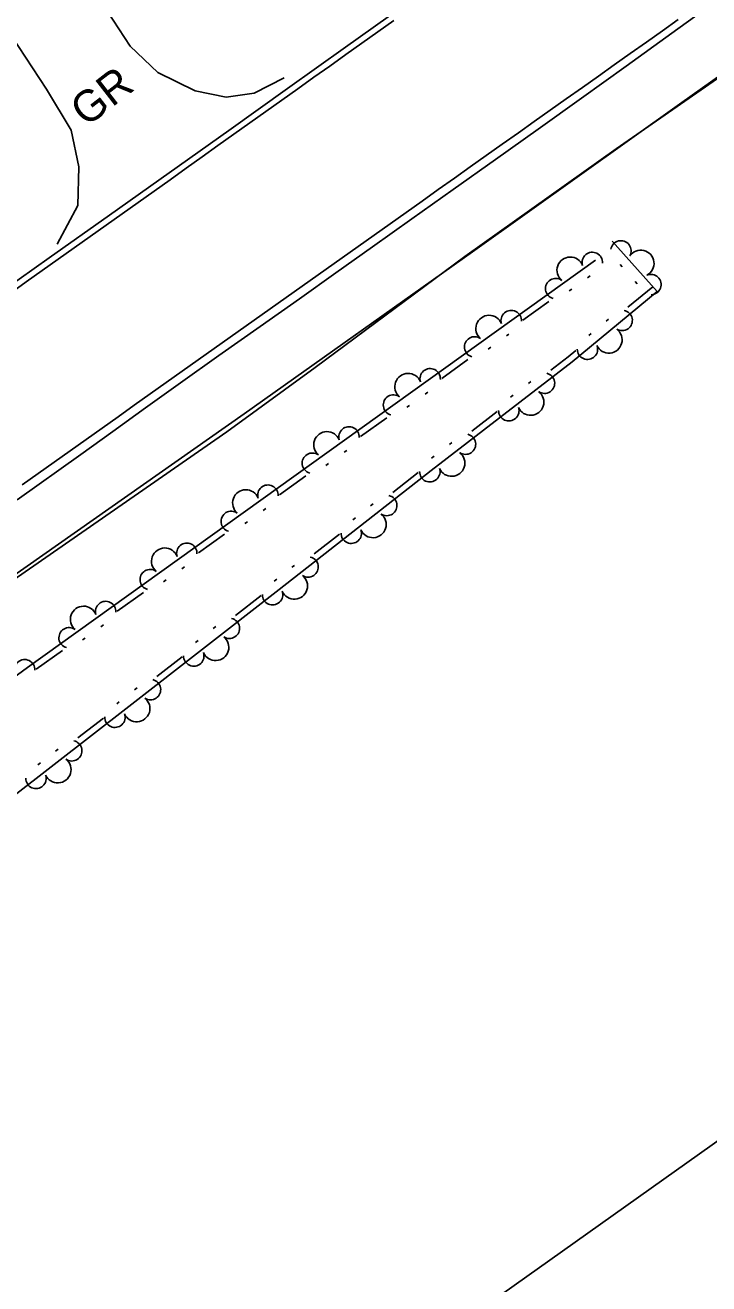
# Model space of a CAD drawing. Extents: x 1577032 to 1581865, y 611492 to 615011.
# Drawn here: x 1580081.3 to 1580168.3, y 613426.5 to 613586.8 of the extents above; entities that cross this region are included whole.
import ezdxf

# ---------------------------------------------------------------- set-up
doc = ezdxf.new("R2010")
doc.units = 0
for name, color, linetype in [('Exist Guardrail', 7, 'Continuous'), ('Exist Right of Way Line', 7, 'Continuous'), ('Exist Roads EOP', 7, 'Continuous'), ('Exist Roads EOT', 7, 'Continuous'), ('Old_Level_11', 7, 'Continuous'), ('Old_Level_7', 7, 'Continuous'), ('Scratch_Level_4', 7, 'Continuous')]:
    doc.layers.add(name, color=color, linetype=linetype)

msp = doc.modelspace()

# ---------------------------------------------------------------- linework, layer by layer
at = {"layer": 'Exist Guardrail'}
msp.add_lwpolyline([(1580204.94, 613604.14), (1580176.13, 613584.66), (1580156.54, 613571.08), (1580137.28, 613557.36), (1580118.21, 613543.22), (1580106.98, 613535), (1580070.56, 613509.77), (1580039.34, 613487.9), (1579996.35, 613458.56), (1579960.14, 613434.1), (1579928.53, 613412.65), (1579891.13, 613387.42), (1579884.09, 613382.52), (1579876.58, 613377.52), (1579866.53, 613371.18), (1579856.35, 613364.93), (1579850.36, 613361.17), (1579845.45, 613357.94), (1579839.56, 613353.95), (1579830.4, 613347.61), (1579818.74, 613338.59)], dxfattribs=at)
at = {"layer": 'Exist Right of Way Line'}
msp.add_line((1578304.92, 612120.6), (1580458.22, 613649.74), dxfattribs=at)
at = {"layer": 'Exist Roads EOP'}
for points in [[(1580129.41, 613589.25), (1580122.09, 613584.03), (1580114.69, 613578.76), (1580107.21, 613573.42), (1580099.64, 613568.03), (1580092.03, 613562.62), (1580084.36, 613557.19), (1580076.66, 613551.75)], [(1580080.28, 613526.36), (1580088.37, 613532.14), (1580092.45, 613535.08), (1580096.62, 613538.08), (1580101.06, 613541.25), (1580105.96, 613544.73), (1580111.21, 613548.44), (1580116.21, 613551.97), (1580120.86, 613555.28), (1580125.51, 613558.58), (1580130.51, 613562.14), (1580135.81, 613565.91), (1580141.19, 613569.73), (1580146.6, 613573.58), (1580152.12, 613577.52), (1580157.81, 613581.61), (1580163.65, 613585.82), (1580169.43, 613589.97)]]:
    msp.add_lwpolyline(points, dxfattribs=at)
at = {"layer": 'Exist Roads EOT'}
for points in [[(1580128.24, 613587.42), (1580126.21, 613585.97), (1580124.17, 613584.52), (1580122.13, 613583.07), (1580120.1, 613581.62), (1580118.06, 613580.18), (1580116.02, 613578.73), (1580113.99, 613577.28), (1580111.95, 613575.83), (1580109.91, 613574.38), (1580107.88, 613572.93), (1580105.84, 613571.49), (1580103.81, 613570.04), (1580101.77, 613568.59), (1580099.73, 613567.14), (1580097.7, 613565.69), (1580095.66, 613564.24), (1580093.62, 613562.8), (1580091.59, 613561.35), (1580089.55, 613559.9), (1580087.51, 613558.45), (1580085.48, 613557), (1580083.44, 613555.55), (1580081.4, 613554.11), (1580079.37, 613552.66)], [(1580080.91, 613528.27), (1580082.95, 613529.72), (1580084.99, 613531.17), (1580087.02, 613532.61), (1580089.06, 613534.06), (1580091.1, 613535.5), (1580093.14, 613536.95), (1580095.18, 613538.4), (1580097.21, 613539.84), (1580099.25, 613541.29), (1580101.29, 613542.73), (1580103.33, 613544.18), (1580105.37, 613545.63), (1580107.4, 613547.07), (1580109.44, 613548.52), (1580111.48, 613549.96), (1580113.52, 613551.41), (1580115.56, 613552.86), (1580117.59, 613554.3), (1580119.63, 613555.75), (1580121.67, 613557.19), (1580123.71, 613558.64), (1580125.75, 613560.09), (1580127.78, 613561.53), (1580129.82, 613562.98), (1580131.86, 613564.42), (1580133.9, 613565.87), (1580135.94, 613567.32), (1580137.97, 613568.76), (1580140.01, 613570.21), (1580142.05, 613571.65), (1580144.09, 613573.1), (1580146.12, 613574.54), (1580148.16, 613575.99), (1580150.2, 613577.44), (1580152.24, 613578.88), (1580154.28, 613580.33), (1580156.31, 613581.77), (1580158.35, 613583.22), (1580160.39, 613584.66), (1580162.43, 613586.11), (1580164.46, 613587.56)]]:
    msp.add_lwpolyline(points, dxfattribs=at)
at = {"layer": 'Old_Level_11'}
for points in [[(1580156.06, 613559.3), (1580161.76, 613552.9), (1580150.95, 613543.94), (1580133.01, 613530.08), (1580113.63, 613514.92), (1580094.48, 613500.02), (1580075.04, 613484.95), (1580051.08, 613466.93), (1580027.89, 613449.31), (1580002.55, 613429.96), (1579984.13, 613415.59), (1579962.72, 613399.84), (1579922.89, 613372.21), (1579876.06, 613342.54), (1579870.92, 613340.95), (1579866.8, 613349.13), (1579884.06, 613361.44), (1579915.37, 613383.81), (1579973.43, 613425.83), (1580032.77, 613469.22), (1580081.59, 613504.98), (1580153.92, 613556.9)], [(1580157.05, 613556.33), (1580157.33, 613556.03)], [(1580152.9, 613554.65), (1580153.23, 613554.89)], [(1580158.96, 613554.19), (1580159.23, 613553.89)], [(1580150.57, 613552.97), (1580150.9, 613553.21)], [(1580161.2, 613553.5), (1580158.05, 613550.88)], [(1580144.66, 613549.24), (1580147.99, 613551.63)], [(1580155.57, 613549.37), (1580155.26, 613549.11)], [(1580142.57, 613547.24), (1580142.9, 613547.47)], [(1580153.36, 613547.54), (1580153.05, 613547.28)], [(1580140.24, 613545.56), (1580140.57, 613545.8)], [(1580134.33, 613541.83), (1580137.67, 613544.22)], [(1580151.41, 613545.39), (1580150.44, 613544.58), (1580148.22, 613542.86)], [(1580145.69, 613541.43), (1580145.37, 613541.18)], [(1580132.24, 613539.82), (1580132.58, 613540.06)], [(1580143.43, 613539.68), (1580143.1, 613539.43)], [(1580129.91, 613538.15), (1580130.24, 613538.39)], [(1580124.01, 613534.42), (1580127.34, 613536.81)], [(1580141.4, 613537.6), (1580138.16, 613535.09)], [(1580135.64, 613533.66), (1580135.31, 613533.41)], [(1580121.91, 613532.41), (1580122.24, 613532.65)], [(1580133.37, 613531.91), (1580133.04, 613531.65)], [(1580119.58, 613530.74), (1580119.91, 613530.98)], [(1580131.35, 613529.82), (1580128.12, 613527.29)], [(1580113.68, 613527), (1580117.01, 613529.4)], [(1580111.58, 613525), (1580111.92, 613525.24)], [(1580125.6, 613525.84), (1580125.28, 613525.59)], [(1580109.25, 613523.32), (1580109.58, 613523.56)], [(1580123.34, 613524.08), (1580123.02, 613523.82)], [(1580103.35, 613519.59), (1580106.68, 613521.98)], [(1580121.33, 613521.98), (1580118.1, 613519.46)], [(1580101.25, 613517.58), (1580101.59, 613517.82)], [(1580115.59, 613518.01), (1580115.26, 613517.76)], [(1580098.92, 613515.91), (1580099.26, 613516.15)], [(1580113.33, 613516.24), (1580113, 613515.99)], [(1580093.02, 613512.18), (1580096.35, 613514.57)], [(1580111.32, 613514.16), (1580108.08, 613511.64)], [(1580090.93, 613510.17), (1580091.26, 613510.41)], [(1580105.56, 613510.2), (1580105.24, 613509.95)], [(1580088.59, 613508.5), (1580088.93, 613508.74)], [(1580103.3, 613508.44), (1580102.97, 613508.19)], [(1580082.69, 613504.77), (1580086.02, 613507.16)], [(1580101.28, 613506.35), (1580098.04, 613503.83)], [(1580095.53, 613502.39), (1580095.2, 613502.14)], [(1580093.26, 613500.63), (1580092.94, 613500.38)], [(1580091.24, 613498.55), (1580088, 613496.04)], [(1580085.48, 613494.6), (1580085.16, 613494.35)], [(1580083.22, 613492.84), (1580082.89, 613492.59)]]:
    msp.add_lwpolyline(points, dxfattribs=at)
for centre, radius, start, end in [((1580157.15, 613558.07), 1.3, 330.1359, 170.9325), ((1580150.7, 613555.6), 1.69, 21.63, 229.7025), ((1580153.51, 613556.6), 1.3, 356.4348, 197.2313), ((1580159.68, 613556.47), 1.69, 297.6647, 145.7372), ((1580148.85, 613553.26), 1.3, 54.1012, 254.8978), ((1580160.97, 613553.78), 1.3, 272.4694, 113.266), ((1580143.18, 613549.19), 1.3, 356.4348, 197.2313), ((1580157.31, 613549.21), 1.3, 238.0866, 78.8832), ((1580140.37, 613548.18), 1.69, 21.63, 229.7025), ((1580155.62, 613546.74), 1.69, 205.6154, 53.6879), ((1580138.52, 613545.84), 1.3, 54.1012, 254.8978), ((1580152.89, 613545.54), 1.3, 180.4202, 21.2167), ((1580130.05, 613540.77), 1.69, 21.63, 229.7025), ((1580132.86, 613541.78), 1.3, 356.4348, 197.2313), ((1580147.42, 613541.21), 1.3, 236.1294, 76.926), ((1580128.19, 613538.43), 1.3, 54.1012, 254.8978), ((1580145.65, 613538.81), 1.69, 203.6582, 51.7307), ((1580142.88, 613537.7), 1.3, 178.4629, 19.2595), ((1580119.72, 613533.36), 1.69, 21.63, 229.7025), ((1580122.53, 613534.37), 1.3, 356.4348, 197.2313), ((1580137.36, 613533.44), 1.3, 236.1294, 76.926), ((1580117.86, 613531.02), 1.3, 54.1012, 254.8978), ((1580135.59, 613531.04), 1.69, 203.6582, 51.7307), ((1580132.82, 613529.93), 1.3, 178.7998, 19.5963), ((1580112.2, 613526.95), 1.3, 356.4348, 197.2313), ((1580109.39, 613525.95), 1.69, 21.63, 229.7025), ((1580127.33, 613525.63), 1.3, 236.4662, 77.2628), ((1580107.53, 613523.61), 1.3, 54.1012, 254.8978), ((1580125.57, 613523.22), 1.69, 203.995, 52.0675), ((1580122.81, 613522.1), 1.3, 178.7998, 19.5963), ((1580099.06, 613518.53), 1.69, 21.63, 229.7025), ((1580101.87, 613519.54), 1.3, 356.4348, 197.2313), ((1580117.31, 613517.8), 1.3, 236.4662, 77.2628), ((1580097.21, 613516.19), 1.3, 54.1012, 254.8978), ((1580115.56, 613515.39), 1.69, 203.995, 52.0675), ((1580112.79, 613514.26), 1.3, 178.6464, 19.4429), ((1580088.73, 613511.12), 1.69, 21.63, 229.7025), ((1580091.54, 613512.13), 1.3, 356.4348, 197.2313), ((1580107.29, 613509.98), 1.3, 236.3128, 77.1094), ((1580086.88, 613508.78), 1.3, 54.1012, 254.8978), ((1580105.53, 613507.57), 1.69, 203.8416, 51.9141), ((1580081.22, 613504.71), 1.3, 356.9968, 197.7934), ((1580102.76, 613506.46), 1.3, 178.6464, 19.4429), ((1580097.25, 613502.18), 1.3, 236.3128, 77.1094), ((1580095.49, 613499.77), 1.69, 203.8416, 51.9141), ((1580092.72, 613498.66), 1.3, 178.5661, 19.3626), ((1580087.21, 613494.38), 1.3, 236.2325, 77.0291), ((1580085.44, 613491.98), 1.69, 203.7613, 51.8338), ((1580082.67, 613490.86), 1.3, 178.5661, 19.3626)]:
    msp.add_arc(centre, radius, start, end, dxfattribs=at)
at = {"layer": 'Old_Level_7'}
msp.add_lwpolyline([(1580204.41, 613605.7), (1580184.66, 613591.04), (1580164.93, 613576.99), (1580138.26, 613557.96), (1580109.19, 613537.33), (1580079.14, 613516.2), (1580044.46, 613491.82), (1580020.63, 613475.12), (1579980.8, 613448.19), (1579942.82, 613422.24), (1579900.08, 613391.73), (1579828.5, 613345.35)], dxfattribs=at)
at = {"layer": 'Scratch_Level_4'}
for points in [[(1579948.7, 613774.09), (1579994.71, 613700.84), (1580013.77, 613671.65), (1580063.46, 613605.63), (1580077.7, 613588.18), (1580084.02, 613578.67)], [(1580091.78, 613588.55), (1580094.64, 613584.17), (1580098.2, 613580.79), (1580102.93, 613578.44), (1580106.87, 613577.66), (1580110.46, 613578.17), (1580114.26, 613580.13)], [(1580084.02, 613578.67), (1580087.16, 613573.44), (1580088.12, 613568.76), (1580088.01, 613563.84), (1580085.34, 613558.91)]]:
    msp.add_lwpolyline(points, dxfattribs=at)

# ---------------------------------------------------------------- texts
msp.add_text('GR', height=4, rotation=37.7966, dxfattribs=at).set_placement((1580089.06, 613573.76))

doc.saveas('drawing.dxf')
